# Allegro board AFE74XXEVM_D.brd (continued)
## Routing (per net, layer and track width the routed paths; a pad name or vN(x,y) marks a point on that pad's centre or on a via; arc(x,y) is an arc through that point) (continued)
RXTDD1: length 148.9
  L4_SIG w0.102: 65.15,57.88 60.36,57.88 59.95,58.29 v1(59.95,58.3)
  L4_SIG w0.127: v1(143.21,58.6) 143.21,53.57 140.63,51 139.95,51 134.49,45.54 85.8,45.54 85.09,44.83 79.32,44.83 66.27,57.88 65.15,57.88
  L8_PWR_SIG w0.127: J9.32 143.5,107.85 145.12,106.23 145.12,105.78 144.55,105.21 144.55,90.42 145.21,89.76 145.21,77.82 145.05,77.65 145.05,77.29 145.2,77.13 145.2,73.32 145.21,73.31 145.21,70.59 143.36,68.73 143.36,58.75 v1(143.21,58.6)
RXTDD2: length 115.5
  TOP w0.127: J9.35 145.69,107.85 144.26,106.41 144.26,105.87 144.41,105.72 144.41,103.64 142.37,101.6 142.37,93.95 140.61,92.2 140.61,86.18 139.11,84.67 123.3,84.67 v1(123.29,84.68)
  L4_SIG w0.102: 60.33,71.5 60.33,69.08 v1(59.95,68.7)
  L4_SIG w0.127: v1(123.29,84.68) 122.58,85.39 121.16,85.39 119.33,83.57 111.38,83.57 110.74,82.93 103.89,82.93 103.38,83.44 102.36,83.44 101.85,82.93 99.29,82.93 98.7,83.52 92.36,83.52 92.16,83.32 89.43,83.32 84.62,78.52 77.76,78.52 77.55,78.73 77.18,78.73 76.86,78.4 66.69,78.4 62.25,73.96 62.25,73.94 61.03,72.72 61.03,72.62 60.33,71.92 60.33,71.5
SDCLKOUT5N: length 4.5
  BOTTOM w0.203: U3.23 96.94,90.11 96.85,90.02 95.77,90.02 95.38,89.62 95.38,88.99 95.2,88.81 94.96,88.81 R194.1 94.23,88.93 C257.1
SDCLKOUT5P: length 4.6
  BOTTOM w0.203: C256.1 94.23,88.27 R193.1 95.06,88.48 95.34,88.48 95.71,88.85 95.71,89.49 95.91,89.69 96.85,89.69 96.94,89.6 U3.22
SDCLKOUT7N: length 3.5
  BOTTOM w0.203: C426.1 R291.1 95.67,94.4 96.12,94.4 96.52,94 96.52,93.73 96.7,93.55 97.26,93.55 97.32,93.61 U3.30
SDCLKOUT7P: length 3.5
  BOTTOM w0.203: U3.29 97.32,93.11 97.21,93.22 96.56,93.22 96.19,93.59 96.19,93.87 95.99,94.07 95.67,94.07 R292.1 94.89,93.9 C425.1
SLEEPMODE: length 140.5
  TOP w0.127: v1(143.99,86.44) 144.25,86.44 145.47,87.66 145.47,93.93 146.84,95.3 146.84,102.13 149.59,104.89 149.59,105.91 v1(149.45,106.05)
  L4_SIG w0.102: v1(61.55,66.3) 61.81,66.3 62.19,66.68 62.52,66.68 62.77,66.93 62.77,67.26 63,67.49 63.28,67.49 63.57,67.78 63.57,68.09 63.78,68.3 65.15,68.3
  L4_SIG w0.127: 65.15,68.3 72.87,68.3 74.04,69.47 138.76,69.47 140.18,70.89 v1(140.46,70.89)
  L6_SIG w0.127: v1(149.45,106.05) 150.27,106.05 150.65,106.43 167.44,106.43 J9.62
  L8_PWR_SIG w0.127: v1(140.46,70.89) 140.72,71.15 140.72,74.6 143.27,77.15 143.27,77.68 143.53,77.94 143.53,85.97 v1(143.99,86.44)
SPIACLK: length 209.3
  TOP w0.127: v1(124.16,115.49) 126.62,113.03 126.62,110.8 126.63,110.78 126.63,104.91 126.62,104.9 126.62,93.37 125.45,92.2 125.45,89.87 126.44,88.87 J13.5
  L6_SIG w0.102: v1(54.35,58.3) 54.21,58.3 53.9,57.99 53.9,57.69 53.93,57.66 53.93,56.54 53.71,56.32 49.15,56.32
  L6_SIG w0.127: 49.15,56.32 48.62,56.32 48.29,56.66 45.43,56.66 42.24,53.46 40.77,53.46 40.45,53.15 40.08,53.15 39.77,53.46 35.5,53.46 34.85,54.11 29.15,54.11 26.3,56.96 26.1,56.96 24.01,59.05 23.39,59.05 23.11,59.34 23.11,61.31 22.49,61.93 22.49,68.62 23.05,69.18 23.05,74.17 23.46,74.58 23.46,85.09 33.47,95.1 33.47,95.95 39.36,101.84 41.75,101.84 46.67,106.77 46.67,107.05 46.93,107.31 47.21,107.31 58.69,118.79 61.51,118.79 62.07,118.23 93.92,118.23 94.46,118.77 111.13,118.77 114.2,115.7 123.95,115.7 v1(124.16,115.49)
SPIASDIO: length 196.4
  TOP w0.127: v1(132.44,109.3) 132.16,109.02 132.16,93.78 130.57,92.19 130.57,89.9 131.52,88.95 J13.11
  L6_SIG w0.102: 49.15,59.51 53.24,59.51 53.55,59.2 v1(53.55,59.1)
  L6_SIG w0.127: v1(132.44,109.3) 132.08,109.65 132.08,110.41 131.15,111.34 129.96,111.34 129.78,111.16 129.28,111.16 128.96,111.48 116.66,111.48 114.86,109.68 110.76,109.68 110.72,109.64 110.36,109.64 110.32,109.68 109.58,109.68 109.57,109.67 108.49,109.67 107.72,110.44 101.47,110.44 100.61,111.3 81.71,111.3 81.59,111.18 74.41,111.18 74.12,110.89 73.75,110.89 73.39,111.26 69.69,111.26 69.69,111.26 65.9,111.26 65.77,111.14 65.4,111.14 65.28,111.26 56.06,111.26 48.31,103.51 47.88,103.51 44.45,100.08 44.17,100.08 43.88,99.79 43.88,99.03 41.78,96.93 40.58,96.93 39.83,96.17 37.98,96.17 36.32,94.52 36.32,93.16 34.95,91.79 34.95,91.05 33.24,89.34 32.84,89.34 32.58,89.08 32.58,88.9 30.55,86.88 30.55,86.31 30.22,85.97 30.22,79.84 30.68,79.39 30.68,77.8 28.07,75.19 28.07,74.08 27.66,73.67 27.66,67.44 28.77,66.33 28.77,64.86 27.5,63.59 27.5,60.98 28.92,59.55 28.92,58.97 29.21,58.68 31.49,58.68 32.62,57.55 41.04,57.55 43.37,59.88 48.78,59.88 49.15,59.51
SPIASDO: length 128.7
  L4_SIG w0.102: v1(53.55,57.5) 53.17,57.12 53.17,56.34 52.32,55.5 49.33,55.5 49.15,55.67
  L4_SIG w0.127: 49.15,55.67 48.55,56.28 48.55,56.4 48.29,56.66 48.17,56.66 46.75,58.08 46.75,58.19 45.98,58.95 45.31,58.95 45.05,59.21 45.05,59.78 43.51,61.32 43.51,63.11 44.16,63.76 44.16,65.49 43.9,65.75 43.9,73.9 42.99,74.82 42.99,80.16 42.98,80.17 42.98,80.54 42.99,80.54 v1(42.99,82.66)
  L6_SIG w0.127: v1(121.74,89.26) 121.92,89.26 122.5,89.84 127.94,89.84 J13.8
  L8_PWR_SIG w0.127: v1(42.99,82.66) 43.03,82.66 47.69,87.32 47.69,87.68 48.15,88.15 48.9,88.15 49.17,87.87 54.6,87.87 56.82,90.09 60.93,90.09 61.8,89.23 71.12,89.23 71.18,89.3 71.55,89.3 71.62,89.23 73.52,89.23 73.58,89.3 73.95,89.3 74.02,89.23 84.5,89.23 85.03,88.7 91.11,88.7 92.11,87.69 93.92,87.69 95.11,88.89 97.14,88.89 97.24,88.79 97.24,88.79 97.68,88.35 109.53,88.35 110.14,88.96 117.46,88.96 117.75,89.26 v1(121.74,89.26)
SPIASEN: length 201.3
  TOP w0.127: J13.2 123.88,88.8 122.86,89.81 122.86,91.92 123.57,92.63 123.57,101.49 122.66,102.4 122.66,102.82 121.95,103.53 121.95,114.22 v1(121.39,114.78)
  L6_SIG w0.102: v1(53.55,58.3) 53.52,58.3 53.13,57.91 53.13,57.34 52.87,57.08 49.15,57.08
  L6_SIG w0.127: v1(121.39,114.78) 121.03,115.14 113.97,115.14 111.69,117.42 74.84,117.42 74.19,116.77 72.8,116.77 72.36,117.21 65.86,117.21 65.86,117.21 64.15,117.21 63.91,116.97 62.42,116.97 61.77,117.61 59.18,117.61 47.74,106.17 47.26,106.17 46.1,105.01 46.1,104.8 43.03,101.73 43.03,101.56 42.77,101.3 41.85,101.3 41.11,100.57 38.76,100.57 33.99,95.79 33.99,94.26 29.67,89.95 29.67,89.7 26.48,86.51 26.48,85.71 24.03,83.26 24.03,65.67 23,64.64 23,63.78 23.78,63 23.78,60.09 25.84,58.04 26.38,58.04 29.08,55.34 32.06,55.34 32.64,54.76 34.98,54.76 35.16,54.94 35.57,54.94 36.44,54.06 38.72,54.06 39.28,54.62 41.67,54.62 44.13,57.08 49.15,57.08
SPIBCLK: length 99.3
  L4_SIG w0.102: v1(54.35,68.7) 53.97,69.08 53.43,69.08 53.13,69.38 53.13,71.5
  L4_SIG w0.127: 53.13,71.5 53.13,72.66 53.13,72.66 53.13,72.9 53.66,73.43 53.66,75.21 54.77,76.32 54.77,80.19 v1(57.48,82.91)
  L6_SIG w0.127: v1(122.48,86.74) 123.01,87.27 135.08,87.27 J13.17
  L8_PWR_SIG w0.127: v1(122.48,86.74) 121.36,85.62 101.73,85.62 101.72,85.61 97.32,85.61 97.18,85.76 95.55,85.76 95.41,85.62 85.62,85.62 83.86,83.87 83.01,83.87 82.27,84.61 67.51,84.61 66.29,83.39 61.34,83.39 61.07,83.66 60.19,83.66 59.44,82.91 v1(57.48,82.91)
SPIBSDIO: length 116.6
  L4_SIG w0.102: v1(53.55,67.9) 53.54,67.9 53.13,68.31 53.13,68.86 52.87,69.12 52.55,69.12 52.33,69.34 52.33,71.5
  L4_SIG w0.127: v1(56.46,86.03) 54.05,83.62 54.05,79.4 53.35,78.7 53.35,75.91 52.66,75.22 52.66,74.1 52.82,73.94 52.82,72.95 52.33,72.46 52.33,71.5
  L6_SIG w0.127: J13.23 140.67,87.78 138.79,87.78 137.85,86.84 137.85,86.16 136.92,85.23 122.72,85.23 118.99,88.96 110.76,88.96 108.93,87.13 108.93,86.88 105.88,83.83 105.88,83.33 105.05,82.5 99.75,82.5 97.38,84.87 96.81,84.87 96.55,85.13 96.18,85.13 95.92,84.87 95.55,84.87 95.13,85.29 92.71,85.29 89.71,88.29 87.01,88.29 86.84,88.46 81.74,88.46 81.63,88.34 70.72,88.34 70.36,88.7 69.95,88.7 69.63,88.38 59.54,88.38 59.04,87.88 58.06,87.88 56.46,86.28 v1(56.46,86.03)
SPIBSDO: length 107.3
  L6_SIG w0.127: J13.20 138.07,89.87 135.94,89.87 135.28,89.2 135.28,88.47 134.59,87.78 123.42,87.78 122.62,88.58 121.32,88.58 v1(121.26,88.52)
  L8_PWR_SIG w0.127: v1(121.26,88.52) 121.23,88.48 119.07,88.48 118.03,87.45 113.13,87.45 112.18,86.5 106.01,86.5 105.17,87.34 99.48,87.34 98.77,86.63 91.96,86.63 91.56,87.02 88.39,87.02 88.19,86.82 84.5,86.82 83.6,87.71 69.49,87.71 69.32,87.88 56.74,87.88 v1(55.4,86.54)
  BOTTOM w0.102: 53.14,71.5 53.14,69.91 v1(53.55,69.5)
  BOTTOM w0.127: 53.14,71.5 52.91,71.73 52.91,73.85 52.66,74.1 52.66,74.91 53.19,75.44 53.19,77.21 52.95,77.45 52.95,80.56 53.62,81.23 53.62,84.76 v1(55.4,86.54)
SPIBSEN: length 105.9
  L6_SIG w0.127: J13.14 132.59,90.27 116.45,90.27 116.19,90 113.75,90 113.61,89.87 111.05,89.87 109.47,88.29 108.97,88.29 104.08,83.4 102.12,83.4 101.84,83.12 100.19,83.12 99.85,83.46 99.85,83.66 97.75,85.76 92.93,85.76 89.31,89.37 58.17,89.37 v1(58.14,89.41)
  BOTTOM w0.102: v1(53.55,68.7) 53.92,69.07 54.45,69.07 54.74,69.36 54.74,71.5
  BOTTOM w0.127: v1(58.14,89.41) 57.86,89.13 57.86,87.99 58.39,87.45 58.39,85.29 54.96,81.85 54.96,75.46 54.4,74.9 54.4,74.53 54.74,74.19 54.74,71.5
STAT 0:
  vias: v1(114.02,88.29)
STAT 1:
  vias: v1(114.05,86.39)
SYNC: length 2.7
  BOTTOM w0.381: U3.6 103.59,85.66 102.74,84.81 R196.2
SYNCB0CMOS: length 221.5
  L4_SIG w0.102: 53.97,55.36 53.97,58.46 54.22,58.72 54.53,58.72 54.91,59.1 v1(55.15,59.1)
  L4_SIG w0.127: 53.97,55.36 53.97,53.58 56.5,51.05 57.05,51.05 58.89,49.22 58.91,49.22 60.55,47.58 60.55,46.99 61.18,46.36 66.89,46.36 69.13,44.12 69.33,44.12 69.62,43.83 69.62,43.63 71.67,41.57 71.67,41.37 78.43,34.62 102.65,34.62 103.33,35.3 103.33,35.89 105.72,38.28 131.24,38.28 131.4,38.44 131.79,38.44 131.95,38.28 148.48,38.28 148.5,38.26 148.87,38.26 148.89,38.28 152.6,38.28 152.91,37.97 189.41,37.97 190.73,39.29 202.08,39.29 203.82,37.55 v1(209.56,37.55)
  L8_PWR_SIG w0.102: 213.55,62.26 209.56,58.27 209.56,38.1
  L8_PWR_SIG w0.127: 209.56,38.1 v1(209.56,37.55) ; v2(210.19,81.91) 210.26,81.91 213.55,78.63 213.55,75.22 213.68,75.09 213.68,74.72 213.55,74.59 213.55,72.75 213.75,72.55 213.75,72.18 213.55,71.98 213.55,62.26
SYNCB1CMOS: length 176.7
  L6_SIG w0.102: v1(59.15,57.5) 59.21,57.5 59.59,57.12 63.27,57.12 63.57,56.82 63.57,56.54 63.8,56.31 65,56.31 65.15,56.16 ; v2(210.19,80.64) 211.89,78.94 211.89,73.89 211.79,73.79 211.79,73.43 211.89,73.33 211.89,62.69 203.48,54.28
  L6_SIG w0.127: 65.15,56.16 67.34,53.97 203.18,53.97 203.48,54.28
SYNCB2CMOS: length 169.8
  L6_SIG w0.102: 203.48,78.77 209.52,78.77 v2(210.19,78.11)
  L6_SIG w0.127: v1(59.36,78.13) 60.45,79.23 64.82,79.23 64.94,79.11 67.88,79.11 68.09,79.32 73.03,79.32 77.27,75.08 77.49,75.08 80.03,72.54 100.79,72.54 101.9,73.65 102.03,73.65 107.17,78.79 203.45,78.79 203.48,78.77
  BOTTOM w0.102: 56.38,71.5 56.38,69.38 56.07,69.07 55.79,69.07 55.58,68.86 55.58,68.33 v1(55.15,67.9)
  BOTTOM w0.127: 56.38,71.5 56.38,72.43 56.69,72.74 56.69,73.11 56.38,73.43 56.38,74.99 58.22,76.84 58.67,76.84 59.36,77.53 v1(59.36,78.13)
SYNCB3CMOS: length 163.3
  L6_SIG w0.102: v2(210.19,76.83) 209.45,77.57 203.48,77.57 ; 59.57,71.5 59.57,69.92 v1(59.15,69.5)
  L6_SIG w0.127: 59.57,71.5 59.57,73.84 64.4,78.67 65.04,78.67 65.3,78.4 73.11,78.4 78.47,73.04 78.47,72.84 79.2,72.11 103.07,72.11 106.22,75.26 106.22,75.57 108.89,78.23 202.69,78.23 203.35,77.57 203.48,77.57
SYSREF+: length 3.6
  BOTTOM w0.203: U3.14 99.58,85.86 99.67,85.78 99.67,84.95 100.1,84.51 100.1,83.74 R174.1 99.95,83.54 R172.1
SYSREF-: length 3.6
  BOTTOM w0.203: U3.13 100.08,85.89 100,85.8 100,85.08 100.43,84.65 100.43,83.72 R173.1 100.56,83.54 R169.1
SYSREF-N: length 13
  L6_SIG w0.102: 49.15,62.59 49.25,62.59 49.35,62.69 51.28,62.69 51.48,62.88 51.62,62.88 51.82,62.68 52.07,62.68 52.28,62.89 52.42,62.89 52.59,62.72 52.6,62.72 52.63,62.68 52.88,62.68 53.08,62.88 53.22,62.88 53.42,62.68 53.82,62.68 53.93,62.79 53.93,63.32 53.82,63.43 53.82,63.63 54.09,63.9 v1(54.35,63.9)
  L6_SIG w0.127: 49.15,62.59 44.22,62.59 44.09,62.71 v1(44.09,62.84)
  BOTTOM w0.203: v1(44.09,62.84) 43.97,62.71 R13.2
SYSREF-P: length 13
  L6_SIG w0.102: v1(54.35,63.1) 54.77,62.68 54.77,62.16 54.53,61.92 49.33,61.92 49.15,62.1
  L6_SIG w0.127: v1(44.09,61.95) 44.09,62.03 44.22,62.15 49.1,62.15 49.15,62.1
  BOTTOM w0.203: R12.2 43.97,62.08 v1(44.09,61.95)
SYSREFN: length 94.7
  L6_SIG w0.127: v1(42.7,62.71) 42.6,62.61 42.09,62.61 41.33,61.85 41.33,61.44 40.26,60.38 36.37,60.38 36.26,60.49 36.26,60.53 36.15,60.65 35.99,60.65 35.88,60.53 35.88,60.49 35.77,60.38 35.41,60.38 34.32,61.47 34.32,62.09 34.43,62.2 34.46,62.2 34.57,62.31 34.57,62.47 34.46,62.58 34.43,62.58 34.32,62.69 34.32,63.07 35.33,64.08 35.33,66.32 38.6,69.6 38.96,69.6 39.07,69.48 39.07,69.48 39.18,69.37 39.34,69.37 39.45,69.48 39.45,69.48 39.57,69.6 40.67,69.6 46.81,75.73 47.11,75.73 48.6,77.22 49,77.22 50.77,78.99 50.77,79.38 52.69,81.3 52.69,81.87 55.88,85.06 61.7,85.06 62.55,85.91 65.17,85.91 66.02,85.06 69.11,85.06 69.12,85.06 70.35,85.06 70.35,85.06 72.18,85.06 72.45,85.33 83.48,85.33 83.7,85.55 84,85.55 84.01,85.56 90.46,85.56 91.47,84.56 91.72,84.56 92.95,83.32 96.48,83.32 97.41,82.4 97.41,81.59 98.53,80.46 99.89,80.46 100.47,81.04 100.47,81.57 v1(100.58,81.69)
  BOTTOM w0.203: v1(100.58,81.69) 100.46,81.81 100.46,82.22 R169.2
SYSREFP: length 94.7
  L6_SIG w0.127: v1(42.7,62.08) 42.6,62.18 42.27,62.18 41.76,61.67 41.76,61.26 40.44,59.95 35.23,59.95 33.88,61.29 33.88,63.25 34.9,64.26 34.9,66.5 38.42,70.03 40.49,70.03 46.63,76.16 46.93,76.16 48.42,77.66 48.83,77.66 50.34,79.17 50.34,79.56 52.26,81.48 52.26,82.05 55.7,85.49 61.52,85.49 62.37,86.34 65.35,86.34 66.19,85.5 69.29,85.5 69.3,85.49 70.17,85.49 70.17,85.5 72,85.5 72.27,85.76 83.3,85.76 83.52,85.99 83.82,85.99 83.83,85.99 90.64,85.99 91.64,84.99 91.9,84.99 93.13,83.76 96.66,83.76 97.84,82.58 97.84,81.77 98.71,80.89 99.71,80.89 100.04,81.22 100.04,81.57 v1(99.92,81.69)
  BOTTOM w0.203: v1(99.92,81.69) 100.08,81.84 100.08,82.19 R172.2
TCLK: length 113.9
  L4_SIG w0.102: 65.15,62.72 61.92,62.72 61.55,63.09 v1(61.55,63.1)
  L4_SIG w0.127: 65.15,62.72 66.14,62.72 66.56,62.29 70.32,62.29 72.75,59.87 142.37,59.87 143.84,61.34 v1(144.04,61.34)
  L8_PWR_SIG w0.127: J10.2 145.81,87.85 145.81,85.86 146.08,85.6 146.08,75.99 145.53,75.44 145.53,75.08 146.33,74.28 146.33,71.11 145.53,70.31 145.53,69.99 144.91,69.37 144.91,62.2 v1(144.04,61.34)
TDI: length 115
  L4_SIG w0.102: v1(61.55,63.9) 61.65,63.9 62.03,63.52 64.11,63.52 64.37,63.78 64.37,64.06 64.62,64.31 65.15,64.31
  L4_SIG w0.127: 65.15,64.31 65.56,64.72 72.97,64.72 74.88,62.81 147.36,62.81 148.89,64.34 v1(148.89,64.74)
  L8_PWR_SIG w0.127: J10.5 149.3,87.78 148.35,86.83 148.35,84.97 148.02,84.64 148.02,81.26 148.44,80.84 148.44,75.53 148.5,75.47 148.5,75.1 148.44,75.04 148.44,65.2 v1(148.89,64.74)
TDO: length 118.3
  L6_SIG w0.102: 65.15,62.7 65.13,62.68 62.19,62.68 61.93,62.42 61.93,61.88 v1(61.55,61.5)
  L6_SIG w0.127: v1(150.95,64.62) 150.14,64.62 148.69,66.07 108.81,66.07 108.24,65.49 108.24,65.17 107.98,64.91 107.66,64.91 106.1,63.35 105.9,63.35 105.63,63.08 78.78,63.08 78.76,63.11 70.59,63.11 70.47,62.98 68.52,62.98 68.15,63.35 65.8,63.35 65.15,62.7
  L8_PWR_SIG w0.127: v1(150.95,64.62) 151.1,64.77 151.1,69.49 152.11,70.5 152.11,79.69 151.74,80.05 151.74,84.66 150.89,85.51 150.89,87.85 J10.8
TMS: length 115.4
  L4_SIG w0.102: v1(61.55,65.5) 61.55,65.42 61.86,65.12 63.31,65.12 63.57,65.38 63.57,65.66 63.83,65.92 64.11,65.92 64.36,66.17 64.36,66.45 64.63,66.72 65.15,66.72
  L4_SIG w0.127: 65.15,66.72 65.37,66.5 75.72,66.5 75.79,66.43 76.16,66.43 76.24,66.52 78.85,66.52 78.95,66.42 151.66,66.42 152.78,67.54 v1(152.78,67.79)
  L8_PWR_SIG w0.127: v1(152.78,67.79) 153.52,68.53 153.52,70.93 153.64,71.06 153.65,71.06 153.96,71.37 153.96,85.3 153.52,85.74 153.52,85.77 153.43,85.86 153.43,87.85 J10.11
TRST: length 120.1
  L4_SIG w0.102: v1(61.55,64.7) 61.93,64.32 63.31,64.32 63.57,64.58 63.57,64.86 63.83,65.12 64.11,65.12 64.37,65.38 64.37,65.66 64.63,65.92 65.15,65.92
  L4_SIG w0.127: v1(155.93,67.84) 155.47,67.84 153.67,66.04 65.27,66.04 65.15,65.92
  L8_PWR_SIG w0.127: J10.14 156.92,88.65 157.87,87.69 157.87,85.35 157.26,84.74 157.26,75.1 157.72,74.64 157.72,70.42 155.93,68.63 v1(155.93,67.84)
  BOTTOM w0.127: R30.1 156.95,88.77 J10.14
TX1ENB: length 220.1
  TOP w0.127: v1(162.89,116.36) 162.89,110.85 162.83,110.78 162.83,108.8 J9.56
  L6_SIG w0.102: 49.15,57.77 49.3,57.92 52.11,57.92 52.13,57.94 52.33,57.94 52.69,58.3 v1(52.75,58.3)
  L6_SIG w0.127: 49.15,57.77 48.92,57.54 46.14,57.54 45.71,57.97 43.57,57.97 42.28,56.68 40.91,56.68 40.86,56.73 40.5,56.73 40.45,56.68 35.94,56.68 34.79,55.52 33.59,55.52 33.35,55.76 30.49,55.76 28.71,57.54 27.71,57.54 24.35,60.91 24.35,62.05 24.7,62.4 24.7,63.33 25.27,63.9 25.27,69.73 25.29,69.75 25.29,71.78 25.46,71.95 25.46,72.32 25.2,72.59 25.2,75.47 24.63,76.04 24.63,82.31 31.09,88.78 31.09,90.6 34.53,94.04 34.53,94.82 36.84,97.13 36.84,97.62 37.94,98.72 38.43,98.72 39.96,100.25 41.82,100.25 42.46,100.89 42.89,100.89 43.86,101.85 43.86,101.86 44.12,102.12 44.13,102.12 45.51,103.5 46.1,103.5 46.36,103.77 46.36,103.91 47.41,104.96 47.64,104.96 57.38,114.7 57.38,114.98 58.42,116.01 62.51,116.01 62.67,116.17 95.79,116.17 96.42,115.54 97.08,115.54 97.46,115.93 112.33,115.93 113.92,114.34 135.67,114.34 135.93,114.08 147.89,114.08 150.47,116.66 162.59,116.66 v1(162.89,116.36)
TX1N: length 14.6
  TOP w0.102: v1(63.15,57.5) 63.15,57.54 63.54,57.93 64.97,57.93 65.15,57.75
  TOP w0.203: 65.15,57.75 65.47,57.43 66.19,57.43 66.4,57.22 66.65,57.22 66.74,57.31 67,57.31 67.18,57.13 67.18,56.88 67.08,56.79 67.08,56.54 72.47,51.16 73.96,51.16 C14.2
TX1P: length 14.6
  TOP w0.102: v1(62.35,57.5) 62.49,57.5 62.92,57.07 62.99,57.07 62.99,57.07 65.15,57.07
  TOP w0.203: C13.2 73.96,50.83 72.33,50.83 66.06,57.1 65.47,57.1 65.44,57.07 65.15,57.07
TX2ENB: length 154.6
  L6_SIG w0.127: v1(56.21,99.47) 58.3,99.47 58.54,99.71 59.71,99.71 60.54,100.53 60.54,101.09 64.24,104.79 64.24,105.24 64.65,105.65 65.15,105.65 67.04,107.55 67.54,107.55 67.76,107.33 71.79,107.33 72.16,106.95 73.72,106.95 74.09,107.33 89.85,107.33 90.65,108.13 94.23,108.13 94.92,107.44 106.38,107.44 107.06,106.76 110.59,106.76 113.49,103.86 126.03,103.86 126.72,104.55 126.72,105.79 127.28,106.35 133.86,106.35 134.11,106.1 135.08,106.1 135.41,106.43 141.05,106.43 141.71,107.09 142.7,107.09 143.1,106.68 146.61,106.68 147.17,107.24 147.17,107.9 148.11,108.84 149.43,108.84 149.68,109.08 150.04,109.08 150.29,108.84 165.4,108.84 166.32,107.92 J9.59
  BOTTOM w0.102: 51.54,71.5 51.54,70.18 51.79,69.93 52.07,69.93 52.37,69.62 52.37,69.19 52.75,68.81 v1(52.75,68.7)
  BOTTOM w0.127: 51.54,71.5 51.41,71.62 51.41,76.52 51.15,76.79 51.15,80.42 51.56,80.84 51.56,84.89 54.71,88.03 54.71,97.06 56.21,98.56 v1(56.21,99.47)
TX2N: length 14
  TOP w0.102: 65.15,59.36 65.02,59.49 63.58,59.49 63.19,59.1 v1(63.15,59.1)
  TOP w0.203: 65.15,59.36 65.51,59 65.87,59 66.05,59.18 66.05,59.33 66.23,59.51 66.48,59.51 66.66,59.33 66.66,59.18 66.84,59 68.13,59 72.93,54.2 73.96,54.2 C16.2
TX2P: length 14
  TOP w0.102: v1(62.35,59.1) 62.78,58.67 65.15,58.67
  TOP w0.203: 65.15,58.67 68,58.67 72.8,53.87 73.96,53.87 C15.2
TX3N: length 13.4
  TOP w0.102: v1(63.15,60.7) 63.42,60.7 63.79,61.07 65.04,61.07 65.15,60.96
  TOP w0.203: C18.2 73.96,57.25 72.4,57.25 69.05,60.6 66.8,60.6 66.62,60.78 66.62,60.93 66.44,61.11 66.19,61.11 66.01,60.93 66.01,60.78 65.83,60.6 65.51,60.6 65.15,60.96
TX3P: length 13.4
  TOP w0.102: v1(62.35,60.7) 62.78,60.27 62.99,60.27 65.15,60.27
  TOP w0.203: C20.2 73.96,56.92 72.26,56.92 68.91,60.27 65.15,60.27
TX4N: length 12.7
  TOP w0.102: v1(63.15,62.3) 63.58,62.73 64.97,62.73 65.15,62.55
  TOP w0.203: 65.15,62.55 65.52,62.18 65.76,62.18 65.94,62.36 65.94,62.48 66.12,62.66 66.37,62.66 66.55,62.48 66.55,62.36 66.73,62.18 71.15,62.18 73.03,60.3 73.94,60.3 C22.2
TX4P: length 12.8
  TOP w0.102: 65.15,61.85 65.13,61.87 62.78,61.87 v1(62.35,62.3)
  TOP w0.203: C24.2 73.94,59.97 72.89,59.97 71.01,61.85 65.15,61.85
TX5N: length 12.7
  TOP w0.102: 65.15,64.45 65.02,64.33 63.52,64.33 v1(63.15,64.7)
  TOP w0.203: 65.15,64.45 65.21,64.51 65.21,64.55 65.4,64.74 65.62,64.74 65.8,64.57 65.8,64.42 65.98,64.24 66.23,64.24 66.41,64.42 66.41,64.57 66.59,64.74 70.68,64.74 72.41,63.02 73.96,63.02 C27.2
TX5P: length 12.7
  TOP w0.102: 65.15,65.07 62.72,65.07 v1(62.35,64.7)
  TOP w0.203: 65.15,65.07 70.82,65.07 72.54,63.35 73.96,63.35 C28.2
TX6N: length 12.1
  TOP w0.102: 65.15,66.05 64.98,65.89 63.56,65.89 v1(63.15,66.3)
  TOP w0.203: C32.2 73.96,66.07 71.73,66.07 71.45,66.34 66.83,66.34 66.65,66.17 66.65,66.02 66.47,65.84 66.22,65.84 66.04,66.02 66.04,66.17 65.86,66.34 65.44,66.34 65.15,66.05
TX6P: length 12.1
  TOP w0.102: 65.15,66.67 62.72,66.67 v1(62.35,66.3)
  TOP w0.203: C30.2 73.96,66.4 71.87,66.4 71.59,66.67 65.15,66.67
TX7N: length 12.4
  TOP w0.102: 65.15,67.65 64.97,67.47 64.53,67.47 64.48,67.53 63.52,67.53 v1(63.15,67.9)
  TOP w0.203: 65.15,67.65 65.49,68 65.95,68 66.13,67.82 66.13,67.69 66.31,67.51 66.56,67.51 66.74,67.69 66.74,67.82 66.92,68 71.75,68 72.87,69.11 73.96,69.11 C35.2
TX7P: length 12.5
  TOP w0.102: v1(62.35,67.9) 62.75,68.3 64.5,68.3 64.53,68.33 65.15,68.33
  TOP w0.203: C36.2 73.96,69.44 72.74,69.44 71.62,68.33 65.15,68.33
TX8N: length 13.1
  TOP w0.102: 65.15,69.31 65.15,69.25 65.02,69.13 63.52,69.13 v1(63.15,69.5)
  TOP w0.203: C38.2 73.96,72.16 72.98,72.16 70.37,69.54 66.84,69.54 66.66,69.37 66.66,69.22 66.48,69.04 66.23,69.04 66.05,69.22 66.05,69.37 65.87,69.54 65.39,69.54 65.15,69.31
TX8P: length 13.1
  TOP w0.102: 65.15,69.87 62.72,69.87 v1(62.35,69.5)
  TOP w0.203: 65.15,69.87 70.23,69.87 72.85,72.49 73.96,72.49 C40.2
TXAM: length 20.4
  TOP w0.203: U1.C20 49.3,57.25 46.87,57.25 R137.2 46.81,57.25 45.95,57.25 42.88,54.18 42.88,52.22 40.91,50.26 L27.1 40.53,50.05 40.47,50.01 36.19,47.45 36.14,47.42 35.77,47.48 35.51,47.78 34.6,47.78 T20.4
TXAP: length 20.4
  TOP w0.203: U1.B20 49.33,56.92 46.96,56.92 46.96,56.92 R137.1 46.84,56.92 46.09,56.92 43.21,54.04 43.21,51.94 40.97,49.71 L28.2 40.59,49.7 36.39,47.19 36.2,46.69 36.35,46.32 36.08,45.62 T20.6
TXBM: length 20.4
  TOP w0.203: U1.F20 49.36,60.09 R141.1 43.48,60.09 40.31,56.92 38.15,56.92 L34.2 37.72,56.95 32.64,56.95 32.4,56.71 32.4,56.41 31.83,55.83 T21.6
TXBP: length 20.4
  TOP w0.203: T21.4 31.82,58.37 32.4,57.79 32.4,57.56 32.69,57.28 37.72,57.28 L33.1 38.2,57.25 40.17,57.25 43.35,60.42 46.68,60.42 46.71,60.45 R141.2 46.82,60.45 46.91,60.45 46.94,60.42 49.27,60.42 U1.G20
TXCM: length 20.4
  TOP w0.203: T22.4 36.09,81.58 36.35,80.63 36.26,80.48 36.35,80.13 40.79,77.57 L35.1 41.15,77.6 41.15,77.42 42.57,76 44.4,76 46.89,73.51 46.89,71.86 47.55,71.2 R145.2 47.55,71.18 47.93,70.8 47.93,70.69 48.79,69.83 49.08,69.83 U1.W20
TXCP: length 20.4
  TOP w0.203: T22.6 34.86,79.36 35.68,79.58 35.8,79.78 36.14,79.87 40.63,77.28 L36.2 41,77.09 42.42,75.67 44.26,75.67 46.56,73.37 46.56,71.7 R145.1 47.6,70.66 47.6,70.55 48.65,69.5 U1.V20
TXDM: length 20.4
  TOP w0.203: U1.P20 49.34,66.51 46.83,66.51 R149.1 46.8,66.51 43.6,66.51 40.51,69.6 38.23,69.6 L42.2 37.76,69.67 32.77,69.67 32.41,69.31 32.41,69.02 31.93,68.54 T23.6
TXDP: length 20.4
  TOP w0.203: U1.R20 49.29,66.84 46.83,66.84 R149.2 46.8,66.84 43.74,66.84 40.65,69.93 38.27,69.93 L41.1 37.86,70 32.69,70 32.43,70.26 32.43,70.59 31.94,71.08 T23.4
TXDSASW: length 154.3
  TOP w0.127: J9.44 152.6,107.85 151.36,109.09 150.9,109.09 150.01,109.98 150.01,112.29 148.89,113.41 v1(148.89,119.94)
  L8_PWR_SIG w0.102: 55.65,71.5 55.53,71.38 55.53,69.08 v1(55.15,68.7)
  L8_PWR_SIG w0.127: 55.65,71.5 57,72.85 57,73.54 60.73,77.27 72.47,77.27 73.93,78.73 84.47,78.73 85.45,79.71 97.08,79.71 98.07,80.7 108.51,80.7 109.42,81.61 120.93,81.61 123.74,84.42 123.74,85.03 122.95,85.81 122.95,92.34 123.7,93.09 123.7,100.3 119.41,104.6 119.41,110.97 121.69,113.26 132.51,113.26 135.36,116.1 144.65,116.1 145.87,117.32 145.87,117.93 147.88,119.94 v1(148.89,119.94)
TXTDD1: length 150.5
  L4_SIG w0.102: v1(52.75,57.5) 52.37,57.12 52.37,56.56 52.07,56.26 51.33,56.26 51.31,56.28 49.26,56.28 49.15,56.38 49.15,56.47
  L4_SIG w0.127: 49.15,56.47 48.08,57.54 47.8,57.54 47.54,57.8 47.54,58.08 46.71,58.92 46.63,58.92 46.32,59.23 46.32,68.94 46.46,69.08 46.46,70.57 46.7,70.81 46.7,73.71 46.14,74.27 46.14,77.74 44.81,79.07 44.81,80.96 45.16,81.31 45.16,95.53 v1(44.78,95.91)
  L6_SIG w0.127: J9.26 137.8,107.85 136.68,108.97 132.73,108.97 132.58,108.81 124.97,108.81 124.36,108.2 124.36,107.47 123.27,106.38 115.88,106.38 115.58,106.09 112.66,106.09 110.91,107.84 107.76,107.84 107.11,108.48 100.97,108.48 100.65,108.8 98.72,108.8 98.67,108.85 96.03,108.85 95.14,109.74 81.32,109.74 80.92,109.34 79.27,109.34 79.01,109.6 78.64,109.6 78.38,109.34 76.73,109.34 76.47,109.6 76.1,109.6 75.55,109.05 73.35,109.05 73.12,109.29 70.38,109.29 70.06,109.61 67.49,109.61 65.81,107.93 64.48,107.93 57.2,100.66 56.54,100.66 51.79,95.91 v1(44.78,95.91)
TXTDD2: length 124.8
  L6_SIG w0.127: v1(57.18,100.08) 57.54,100.08 64.51,107.04 65.96,107.04 66.79,107.88 67.16,107.88 67.84,108.56 93.95,108.56 94.15,108.76 95.45,108.76 95.89,108.33 96.63,108.33 96.73,108.43 97.1,108.43 97.14,108.39 100.14,108.39 100.58,107.95 106.63,107.95 107.25,107.33 110.73,107.33 113.7,104.36 123.6,104.36 124.26,105.02 124.26,106.02 125.07,106.83 133.81,106.83 134.19,107.21 134.85,107.21 135.2,106.86 139.93,106.86 J9.29
  BOTTOM w0.102: v1(52.75,69.5) 52.75,69.7 52.35,70.1 52.35,71.22 52.07,71.5
  BOTTOM w0.127: 52.07,71.5 51.93,71.64 51.93,77.21 51.83,77.31 51.83,77.94 52.16,78.27 52.16,84.47 55.33,87.64 55.33,97.03 57.09,98.78 57.09,99.99 v1(57.18,100.08)
U16_FB: length 8.9
  TOP w0.305: R243.1 156.69,17.12 ; U16.2 155.21,14.99 C340.2 155.3,15.01 155.7,15.42 155.7,15.43 155.85,15.58 155.87,15.58 R237.2
  TOP w0.508: R321.1 156.69,17.12 156.41,16.84 R243.1 R245.2 R237.2 R239.2
U16_SW: length 1.1
  TOP w0.305: U16.7 152.71,12.41 153.21,12.41 U16.6
USB_DM: length 10.6
  TOP w0.203: R211.2 193.83,114.45 C291.1
  TOP w0.229: U5.7 192.07,107 192.13,107.06 192.68,107.06 193.56,107.94 193.56,113.63 193.75,113.82 C291.1
USB_DP: length 10
  TOP w0.203: C290.1 192.91,114.45 R212.2
  TOP w0.229: U5.8 192.07,107.5 192.13,107.44 192.52,107.44 193.18,108.1 193.18,113.63 192.99,113.82 C290.1
USB_EECLK: length 3
  TOP w0.127: U5.62 187.81,99.14 U8.2
  vias: v1(187.83,98.55)
USB_EECS: length 3.1
  TOP w0.127: U8.1 188.48,100.37 188.31,100.53 U5.63
  vias: v1(188.54,99.59)
USB_REF: length 1.6
  BOTTOM w0.254: R214.1 189.24,106.5 v3(190.69,106.5)
USB_RST: length 1.8
  TOP w0.305: v1(188.87,110.49) 188.88,110.5 U5.14
VADJ:
  vias: v1(212.62,91.74) v2(206.38,38.73) v2(207.65,40) v2(208.92,38.73) v2(210.19,40)
VIO_B_M2C:
  vias: v2(203.84,38.73) v2(205.11,40)
VREF_A_M2C: length 8.8
  TOP w0.254: v2(206.38,88.27) 206.38,89.81 TP4.1
VREF_B_M2C: length 4.9
  TOP w0.254: TP5.1 198.98,88.27 v2(203.84,88.27)
Y2_N: length 5.9
  BOTTOM w0.381: R184.1 103.84,102.77 R185.1 103.84,104.22 104.22,104.6 106.1,104.6 Y1.4
Y2_P: length 6.1
  BOTTOM w0.381: R178.1 103.17,102.77 R179.1 103.17,104.52 105.69,107.03 Y1.5
YO2_N: length 0.7
  BOTTOM w0.381: C251.1 R184.2
YO2_P: length 0.7
  BOTTOM w0.381: C244.1 R178.2
N16791764: length 5.2
  TOP w0.305: J33.1 193.24,119.13 194.74,117.63 R210.2
N16791900: length 11.5
  BOTTOM w0.305: v3(190.73,105.51) v3(189.92,105.51) 189.99,105.44 C282.1 190.65,105.44 v3(190.73,105.51) ; v3(190.73,105.51) 191.01,105.23
  BOTTOM w0.508: 190.2,105.23 189.99,105.44 ; 190.2,105.23 190.63,104.8 FB14.2 ; 190.2,105.23 C283.1 191.67,105.23 ; FB14.2 192.79,104.83 192.79,105.21 ; FB14.2 192.81,105.21 192.79,105.21 ; 192.79,105.21 192.79,105.23 191.67,105.23 ; 191.67,105.23 192.81,104.09
  BOTTOM w0.762: FB14.2 FB15.2
N16791904: length 3.9
  BOTTOM w0.305: C272.1 191.08,108 v3(190.2,108)
  BOTTOM w0.508: C272.1 190.22,108.03 v3(190.2,108)
  BOTTOM w0.762: FB12.2 192.99,107.77 191.36,107.77 C272.1
  vias: v3(191.26,108)
N16792068: length 1.7
  BOTTOM w0.305: R216.2 R215.1 R213.2
N16792392: length 0.8
  BOTTOM w0.127: R220.2 R219.1
  vias: v1(186.53,99.13)
N16935212: length 6
  TOP w0.127: U5.21 186.81,115.95 184.72,118.05 184.29,118.05 U6.15
N16935240: length 13.9
  TOP w0.127: U6.20 v1(183.4,121.14) ; U5.16 v1(190.69,112.26)
  BOTTOM w0.127: v1(190.69,112.26) 185.14,117.81 185.14,120.14 184.1,121.18 183.44,121.18 v1(183.4,121.14)
N16935242: length 7.7
  TOP w0.127: U5.18 188.31,115.5 184.73,119.08 184.31,119.08 U6.17
N17033323: length 1.1
  BOTTOM w0.508: R209.1 194.46,103.61 FB15.1
N17033325:
  vias: v1(196.47,103.61)
N17828171:
  vias: v1(195.61,93.11) v1(195.61,91.84) v1(196.8,93.06) v1(196.83,91.81) v1(197.97,93.08) v1(198,91.84)
N17829143: length 5
  TOP w0.305: U4.3 193.49,89.77 192.82,89.09 190.99,89.09 190.45,89.63 R208.1
N17906763: length 3
  TOP w0.381: J31.1 103.4,81.43 102.74,82.09 v1(102.74,82.96)
N18051729: length 6.6
  TOP w0.127: U5.38 178.34,109 178.16,108.81 178.16,108.15 175.53,105.53 U9.20
N18051775: length 7.3
  TOP w0.127: U9.18 v1(177.13,103.74)
  BOTTOM w0.127: v3(179.44,108.5) 179.43,108.48 178.03,108.48 177.13,107.59 v1(177.13,103.74)
N18051825: length 7.1
  BOTTOM w0.127: v3(176.61,103.24) 177.26,103.24 177.58,103.55 177.58,107.45 178.13,108 179.44,108 v3(179.44,108)
N18051839: length 7
  BOTTOM w0.127: v3(176.61,102.74) 177.26,102.74 177.9,103.38 177.9,107.14 178.26,107.49 179.44,107.49 v3(179.44,107.5)
N18199775: length 1.9
  BOTTOM w0.381: C252.1 103.84,99.01 R186.1 R181.2 103.84,100.84 C251.2
N18276385: length 12.5
  TOP w0.203: v1(98.35,96.62) 98.92,96.62 99.12,96.82 99.12,100.92 96.55,103.49 96.3,103.49 96.2,103.39 95.95,103.39 95.77,103.57 95.77,103.82 95.87,103.92 95.87,104.17 95.7,104.34 95.2,104.34 v1(95.05,104.19)
  BOTTOM w0.203: v1(95.05,104.19) 94.88,104.36 94.59,104.36 94.51,104.27 U2.11
N18284119: length 12.5
  TOP w0.203: v1(100.23,96.62) 99.66,96.62 99.45,96.82 99.45,101.05 95.83,104.67 95.22,104.67 v1(95.05,104.85)
  BOTTOM w0.203: U2.10 94.51,104.77 94.59,104.69 94.88,104.69 v1(95.05,104.85)
N18332593: length 1.6
  BOTTOM w0.305: v1(89.94,105.56) 90.23,105.27 U2.4 ; U2.5 v1(90.96,106.12) ; U2.1 v1(90.55,103.38)
N18332757: length 4.6
  TOP w0.127: U5.23 185.78,113.41 185.78,116.03 184.76,117.04 U6.13
N18476239: length 12.6
  TOP w0.508: v1(104.04,109.52) 109.7,103.86 JP1.1
N18554997: length 1.5
  TOP w0.305: D12.1 179.15,13.72 R221.2
N18555159: length 3.2
  TOP w0.508: v5(188.26,14.6) 188.26,16.21 187.91,16.56 186.84,16.56 U12.4
N18858492: length 1.4
  BOTTOM w0.381: v1(36.63,61.62) 37.47,61.62 R322.2
N18858499: length 1.8
  BOTTOM w0.381: R4.1 R7.1 C4.2
N18858501: length 1.4
  BOTTOM w0.381: v1(36.63,63.04) 37.57,63.04 R323.2
N18864728: length 0.9
  TOP w0.305: Q22.1 R204.2
N18864745: length 54.2
  L4_SIG w0.127: v1(201.19,30.68) 196.72,30.68 195.88,29.85 v1(192.84,29.85)
  L8_PWR_SIG w0.102: 203.48,52.76 203.48,53.01 212.04,61.57 212.04,65.99 v2(212.73,66.67)
  L8_PWR_SIG w0.127: 203.48,52.76 198.82,48.11 198.4,48.11 193.12,42.82 193.12,33.72 192.6,33.2 192.6,30.09 v1(192.84,29.85)
N18864749: length 0.9
  TOP w0.305: Q23.1 R206.2
N18864761: length 45.1
  L8_PWR_SIG w0.127: v1(191.34,30.76) 190.42,31.67 190.42,41.29 199.59,50.46 199.76,50.46 208.25,58.95 208.25,59.21 210.92,61.87 210.92,66.14 v2(211.46,66.67)
N18864763: length 54
  L4_SIG w0.127: v1(196.04,30.73) 195.63,30.33 192.41,30.33 v1(191.92,29.85)
  L8_PWR_SIG w0.102: v2(211.46,67.94) 209.75,66.24 209.75,61.79 203.48,55.52
  L8_PWR_SIG w0.127: v1(191.92,29.85) 191.11,29.85 189.92,31.04 189.92,41.28 189.98,41.34 189.98,41.71 189.92,41.78 189.92,42.8 194.96,47.84 195.87,47.84 199.57,51.54 199.57,52.19 201.95,54.57 202.98,54.57 203.24,54.83 203.24,55.28 203.48,55.52
N18864798: length 0.9
  TOP w0.305: R203.2 Q22.3
N18864814: length 0.9
  TOP w0.305: Q21.1 R202.2
N18865554: length 2.2
  TOP w0.305: D9.2 196.55,35.92 R203.1
N18865572: length 2.2
  TOP w0.305: D8.2 201.7,35.86 R201.1
N18865624: length 2.2
  TOP w0.305: D10.2 191.85,35.94 R207.1
N18865630: length 4
  TOP w0.127: R205.1 202.92,64.77 203.48,64.77
  TOP w0.152: 203.48,64.77 205.74,64.77 v2(206.38,65.41)
N18883805: length 2.9
  BOTTOM w0.381: v1(32.3,44.96) C187.2 ; C187.2 C189.2 ; C187.2 32.77,46.32
N18883857: length 1.8
  TOP w0.381: R136.2 R138.1 C184.2
N18883928: length 1.8
  TOP w0.381: R140.2 R142.1 C195.2
N18883944: length 3
  BOTTOM w0.381: v1(28.2,57.1) C199.2 ; C199.2 C201.2 ; C199.2 C198.2
N18884373: length 2.6
  TOP w0.381: T20.3 C185.2 C184.1
N18884375: length 2.8
  TOP w0.381: T21.3 C197.2 C195.1
N18885333: length 2.8
  BOTTOM w0.381: C206.2 33.38,81.74 C208.2 ; C206.2 v1(32.37,82.26) ; C206.2 C205.2
N18885345: length 1.8
  TOP w0.381: R144.2 R146.1 C202.2
N18885353: length 1.8
  TOP w0.381: C214.2 R150.1 R148.2
N18885357: length 2.9
  BOTTOM w0.381: v1(28.2,69.81) C218.2 ; C218.2 C220.2 ; C218.2 C217.2
N18885439: length 2.7
  TOP w0.381: C202.1 C204.2 T22.3
N18885440: length 2.7
  TOP w0.381: C214.1 C216.2 T23.3
N18893180: length 3.2
  TOP w0.381: C133.1 45.62,41.3 arc(45.86,40.58) 45.81,39.83 T5.6
N18962088:
  vias: v1(182.09,33.17) v1(182.07,32.21) v1(183.11,33.17) v1(183.08,32.21) v1(184.02,32.21) v1(184.05,33.17)
N18962090:
  vias: v1(178.75,27.42)
N18962122: length 0.3
  BOTTOM w0.381: v1(177.45,27.42) 177.65,27.61 R222.2
N18962132: length 0.2
  BOTTOM w0.381: R223.2 176.73,27.49 v1(176.8,27.42)
N18962213: length 0.4
  BOTTOM w0.381: v1(175.5,28.72) 175.71,28.72 R224.2
N18963933:
  vias: v1(114.12,9.42)
N18963939: length 2.2
  TOP w0.305: v1(112.5,15.47) 112.42,15.39 C353.1 112.42,14.61 v1(112.5,14.53) 112.5,13.47 C451.1
  vias: v1(112.57,13.64) v1(112.57,12.7) v1(114.35,15.49) v1(114.35,14.53) v1(114.35,13.59) v1(115.6,15.52) v1(115.6,14.55) v1(115.6,13.61)
N18963949:
  vias: v1(119.35,10.09)
N18963966: length 0.3
  TOP w0.381: U20.6 v1(115.4,8.14)
  BOTTOM w0.381: v1(115.4,8.14) 115.27,8.27 R253.2
N18963972: length 1.8
  TOP w0.305: C358.1 112.6,10.74 U20.3
N18963976: length 0.2
  BOTTOM w0.381: R254.2 116.21,8.25 v1(116.09,8.14)
N18964074: length 2.6
  TOP w0.254: R249.1 117.45,14.73 R250.1
  TOP w0.305: R249.1 116.54,16.81 PP8.1
N18964185: length 0.5
  BOTTOM w0.305: v1(117.55,15.65) 117.49,15.58 U19.1
N18964329: length 1.9
  TOP w0.305: U20.13 121.21,10.74 C361.1
N18992157: length 0.1
  BOTTOM w0.305: v1(129.1,21.07) 129.03,21.14 R282.2
N18992183: length 2.2
  TOP w0.203: C456.1 126.21,26.78 C415.1 v1(126.47,28.65)
  vias: v1(126.34,26.95) v1(126.34,26.01) v1(126.44,27.81) v1(127.94,27.74) v1(127.97,28.6) v1(128.02,26.85) v1(128.02,26.01) v1(129.08,26.85) v1(129.08,26.01) v1(129.21,28.6) v1(129.18,27.74)
N18992193:
  vias: v1(133.01,23.02)
N18992197: length 0.2
  BOTTOM w0.305: v1(129.75,21.07) 129.87,21.19 R283.2
N18992199: length 1.7
  TOP w0.305: U29.3 126.31,23.67 C419.1
N18992203:
  vias: v1(131.05,21.07)
N18992243: length 2.8
  TOP w0.254: R281.1 131.01,27.74 R280.1
  TOP w0.305: R280.1 PP28.1
N18992297: length 0.5
  BOTTOM w0.305: U30.1 131.07,28.61 v1(131.11,28.65)
N18992349: length 1.8
  TOP w0.305: C421.1 134.8,23.67 U29.13
N18994871: length 0.3
  TOP w0.305: U29.10 131.76,21.01 v1(131.95,21.01)
N19007167: length 2.7
  TOP w0.305: v3(153.21,7.58) 153.21,7.37 v1(152.65,6.81)
  BOTTOM w0.305: v3(153.21,7.58) 153.21,6.98 R234.2 152.7,6.76 v1(152.65,6.81)
  vias: v1(148.56,8.05) v1(148.56,6.96) v1(149.4,7.47) v1(149.94,4.88) v1(149.94,2.79) v1(149.96,3.84) v1(150.85,4.88) v1(150.88,3.84) v1(150.85,2.79) v1(151.82,4.9) v1(151.84,3.86) v1(151.82,2.82)
N19009214: length 3
  TOP w0.305: C328.1 154.71,6.31 v3(154.71,7.22) U16.20
  BOTTOM w0.305: v3(154.71,7.94) v3(154.71,7.22) 154.71,7.01 R234.1
N19009493: length 3.4
  TOP w0.203: U16.21 155.21,6.96 155.39,6.78 155.95,6.78 156.15,6.57 C501.1 156.96,5.75 Q26.3
N19010016: length 1
  TOP w0.305: R235.1 153.1,14.09 C327.2
N19010394: length 7.3
  BOTTOM w0.305: 147.42,19.33 147.5,19.41 153.64,19.41 v1(154.36,18.69)
  vias: v1(145.54,14.2) v1(145.54,13.34) v1(146.74,14.22) v1(146.71,13.36) v1(147.4,18.01) v1(147.4,16.69) v1(147.4,15.49) v1(147.83,13.36) v1(147.85,14.2) v1(149,14.2) v1(149.02,13.36)
N19011515: length 1.4
  BOTTOM w0.254: v1(143.48,10.87) 144.4,11.79 R241.1
N19011541:
  vias: v1(139.17,14.81) v1(139.17,13.92) v1(140.31,14.81) v1(140.3,13.93) v1(140.89,18.62) v1(140.89,17.6) v1(140.89,16.71) v1(141.14,13.8) v1(141.15,19.38) v1(141.78,18.24) v1(141.78,17.22) v1(142.11,13.8) v1(142.16,19.13)
N19011602:
  vias: v1(143.48,11.89)
N19016825: length 0.9
  TOP w0.305: C338.2 154.38,15.93 R237.1
N19016841: length 3.5
  TOP w0.305: 155.27,16.92 R239.1 154.38,16.84 C338.1 R240.2 154.38,17.7 R301.2 155.27,16.92
N19016961: length 0.9
  TOP w0.305: R245.1 C342.2
N19016975: length 3.9
  TOP w0.305: C342.1 C340.1 156.21,12.75 155.71,12.25 U16.1
N19024858:
  vias: v1(150.09,13.92)
N19030259: length 0.4
  BOTTOM w0.305: v3(153.72,7.47) 153.85,7.59 R244.1
N19030918: length 1.8
  TOP w0.203: C341.1 154.21,6.44 U16.19
N19075291: length 0.1
  BOTTOM w0.254: R31.2 51.16,69.51 v1(51.15,69.5)
N19075362:
  vias: v1(51.15,68.7)
N19075631: length 132.7
  L6_SIG w0.127: v1(68.92,118.8) 68.92,119.17 69.94,120.19 70.72,120.19 70.94,119.96 132.18,119.96 136.96,115.19 J11.1
  BOTTOM w0.102: 55.55,71.5 55.55,69.34 55.28,69.07 54.99,69.07 54.74,68.82 54.74,68.53 54.51,68.3 54.22,68.3 53.95,68.03 53.95,65.15 53.55,64.75 v1(53.55,64.7)
  BOTTOM w0.127: 55.55,71.5 55.72,71.67 55.72,75.73 58.86,78.87 59.17,78.87 62.2,81.9 62.2,87.72 62.82,88.34 62.82,97.37 64.58,99.12 64.58,99.52 65.36,100.31 65.77,100.31 67.47,102.01 67.47,106.18 66.91,106.74 66.91,107.29 67.51,107.88 67.51,113.84 68.92,115.25 v1(68.92,118.8)
N19075640: length 142.7
  L4_SIG w0.102: 65.15,61.9 59.56,61.9 59.16,61.5 v1(59.15,61.5)
  L4_SIG w0.127: 65.15,61.9 67.87,61.9 72.52,57.25 138.68,57.25 v1(139.95,58.52)
  L8_PWR_SIG w0.127: v1(139.95,58.52) 139.95,58.86 138.49,60.32 138.15,60.32 137.49,60.99 137.49,81.31 137.59,81.41 137.59,92.15 136.78,92.96 136.78,104.9 136.79,104.91 136.79,110.78 136.78,110.8 136.78,111.86 139.5,114.58 J11.3
N19075649: length 136.2
  TOP w0.127: J11.5 142.93,115.04 147.04,110.92 147.04,103.84 144.92,101.71 144.92,88.3 144.68,88.06 v1(144.68,87.96)
  L4_SIG w0.102: 65.15,67.52 63.83,67.52 63.53,67.22 63.53,66.14 63.27,65.88 59.53,65.88 v1(59.15,65.5)
  L4_SIG w0.127: v1(144.17,70.76) 143.84,70.76 141.92,68.85 81.03,68.85 80.96,68.92 74.26,68.92 72.85,67.52 65.15,67.52
  L8_PWR_SIG w0.127: v1(144.68,87.96) 144.77,87.87 144.77,81.98 144.46,81.68 144.46,80.23 144.68,80.02 144.68,75.46 144.69,75.44 144.69,71.29 v1(144.17,70.76)
N19075658: length 134.3
  L4_SIG w0.102: v1(63.95,63.1) 64.21,63.1 64.59,63.48 65.15,63.48
  L4_SIG w0.127: 65.15,63.48 67.47,63.48 68.07,64.08 71.83,64.08 75.58,60.34 138.21,60.34 139.32,61.45 v1(139.32,61.72)
  L8_PWR_SIG w0.127: J11.7 144.58,114.83 142.39,112.65 142.39,106.72 142.41,106.71 142.41,101.28 142.38,101.26 142.38,92.47 142.77,92.08 142.77,89.94 142.56,89.72 142.56,89.35 142.77,89.13 142.77,82.67 143.09,82.35 143.09,81.98 142.67,81.57 142.67,77.27 139.34,73.94 139.34,61.75 v1(139.32,61.72)
N19075667: length 136.3
  L4_SIG w0.102: 65.15,65.08 64.59,65.08 64.37,64.86 64.37,64.57 63.95,64.15 v1(63.95,63.9)
  L4_SIG w0.127: v1(146.91,64.77) 146.9,64.76 146.11,64.76 144.7,63.35 75.79,63.35 73.81,65.33 65.4,65.33 65.15,65.08
  L8_PWR_SIG w0.127: v1(146.91,64.77) 146.89,64.8 146.89,84.68 147.85,85.65 147.85,91.74 147.02,92.58 147.02,114.94 J11.9
N19080738: length 10.2
  TOP w0.508: JP1.2 112.39,99.46 C248.2 C246.2 C243.2 C242.2 110.88,108.12 FB1.1
N19081029:
  vias: v1(109.82,110.83)
N19083254: length 36.4
  L8_PWR_SIG w0.127: v1(113.06,82.6) 112.97,82.51 97.37,82.51 95.22,84.66 v1(94.56,84.66)
  BOTTOM w0.127: v1(94.56,84.66) 92.27,86.96 92.27,93.83 92.95,94.51 93.42,94.51 94.59,95.68 95.73,95.68 97.31,94.11 U3.31
N19083268: length 17
  TOP w0.127: v1(113.06,84.51) 112.52,85.04 112.52,92.81 109.32,96.01 v1(108.79,96.01)
  BOTTOM w0.127: U3.48 106.09,95.8 106.57,96.28 108.52,96.28 v1(108.79,96.01)
N19083286: length 7.5
  BOTTOM w0.127: U3.59 108.13,89.6 108.46,89.28 110.15,89.28 113.03,86.4 R198.2
N19083328: length 6.8
  BOTTOM w0.127: U3.58 108.52,90.11 108.78,89.85 110.43,89.85 111.96,88.32 R197.2
N19083344:
  vias: v3(100.58,86.61)
N19083346: length 1.2
  TOP w0.305: v3(101.09,86.28) 101.09,85.5 C268.1
N19083364: length 1.5
  TOP w0.305: v3(101.57,85.95) 101.6,85.98 v3(101.6,86.61)
  TOP w0.381: v3(98.6,95.1) 98.6,95.68 v3(98.4,95.88)
  vias: v3(98.58,95.51) v3(100.08,95.77) v3(100.08,95.1)
N19083444: length 0.7
  TOP w0.381: v3(101.6,95.1) 101.6,95.8 v3(101.59,95.82)
N19083446: length 0.6
  TOP w0.381: v3(104.57,95.12) FB9.2 104.57,95.73 v3(104.6,95.76)
N19083508: length 1.1
  TOP w0.203: v3(105.59,95.31) v3(105.59,95.66)
  BOTTOM w0.305: v3(105.59,95.31) U3.47 v3(105.59,95.66) v3(105.59,96.02)
N19083566: length 0.6
  TOP w0.381: v3(97.38,89.13) 97.41,89.1 v3(97.99,89.1)
N19083568: length 4.7
  TOP w0.305: v3(97.41,87.12) 97.37,87.08 97.37,86.72 ; v3(97.41,87.12) 97.46,87.07 97.99,87.07 ; v3(97.41,87.12) 97.43,87.12 97.56,87.25 97.82,87.25 97.99,87.07 ; v3(97.41,87.12) 97.41,86.72 ; 97.41,86.72 97.68,86.72 v3(98.06,87.1) ; 97.41,86.72 97.37,86.72 ; 97.37,86.72 FB5.2 97.67,86.29 98.04,86.66 98.04,87.02 97.99,87.07
N19083616: length 6.2
  TOP w0.305: 107.07,86.32 107.07,86.11 FB11.2 ; 107.07,86.32 107.08,86.32 ; 107.07,86.32 106.86,86.32 106.68,86.5 106.68,87.01 v3(106.59,87.1) 106.86,87.1 ; 106.86,87.1 107.08,87.1 ; 106.86,87.1 106.86,86.56 107.08,86.34 ; 107.08,87.1 107.08,86.34 ; 107.08,87.1 v3(107.25,87.1) ; 107.08,87.1 107.24,86.94 ; 107.08,86.34 107.08,86.32 ; FB11.2 107.31,86.13 107.53,86.35 107.53,86.78 107.36,86.94 107.24,86.94 ; FB11.2 107.24,86.18 107.24,86.32 ; 107.08,86.32 107.24,86.32 ; 107.24,86.94 107.24,86.32
N19083618: length 2.1
  TOP w0.381: v3(107.44,92.58) 106.4,92.58 v3(106.78,92.61)
  BOTTOM w0.305: v3(107.44,92.58) 107.42,92.61 U3.53 106.78,92.61 v3(106.78,92.61)
N19083707: length 0.8
  TOP w0.381: v3(97.99,91.59) FB4.2
  vias: v3(97.38,91.63)
N19086842: length 4.1
  BOTTOM w0.203: C229.1 96.76,83.29 R168.1 97.49,84.01 97.99,84.01 98.67,84.69 98.67,85.37 98.58,85.46 U3.16
N19086844: length 4.3
  BOTTOM w0.203: C228.1 97.89,83.51 R167.1 99,84.56 99,85.37 99.08,85.46 U3.15
N19098122: length 1.8
  TOP w0.381: C127.2 44.73,42.88 L3.2 45.03,43.94 C129.2
N19098132: length 1.8
  TOP w0.381: C130.2 46.04,43.72 L3.1 45.7,42.46 C133.2
N19098142: length 1.7
  TOP w0.381: 46.09,44.5 46.36,44.78 L5.1 46.63,45.85 R58.2
N19098149: length 1.8
  TOP w0.381: R48.2 45.66,46.12 L5.2 45.33,45.01 C129.1
N19098687: length 0.7
  TOP w0.381: R48.1 C131.2
N19098701: length 0.7
  TOP w0.381: C136.2 R58.1
N19189047: length 6.1
  TOP w0.381: v1(92.99,90.17) 91.39,90.17 90.35,91.21 90.35,92.08 89.44,92.99 J27.1
N19189049: length 6.1
  TOP w0.381: J28.1 92.71,94.98 91.77,94.04 91.77,93.05 92.99,91.83 v1(92.99,90.78)
N19191731: length 1.4
  BOTTOM w0.381: T2.2 23.04,63.26 arc(22.56,63.16) R4.2
N19192217: length 5
  BOTTOM w0.381: R8.2 28.18,62.62 28.37,62.81 31.53,62.81 R9.1 C7.1
N19192242: length 1.5
  BOTTOM w0.381: T3.2 34.51,62.33 arc(33.97,62.44) C7.2
N19192342: length 1.4
  BOTTOM w0.381: T2.4 25.53,62.55 25.54,62.55 26.55,62.55 R8.1
N19192872: length 4.9
  BOTTOM w0.381: R1.2 28.22,64.03 28.35,64.16 R2.1 C1.1
N19192989: length 1.4
  BOTTOM w0.381: R1.1 26.48,63.97 T2.6
N19193468: length 127
  L4_SIG w0.102: v1(51.15,57.5) 50.77,57.12 49.59,57.12 49.15,57.55
  L4_SIG w0.127: 49.15,57.55 47.28,59.42 47.28,70.9 47.08,71.11 47.08,75.92 46.72,76.28 46.72,77.33 46.87,77.47 46.87,82.18 45.77,83.28 45.77,95.56 55.14,104.94 56.45,104.94 60,108.49 65.14,108.49 65.41,108.77 67.16,108.77 67.21,108.71 95.03,108.71 95.07,108.75 95.43,108.75 95.47,108.71 110.11,108.71 111.12,109.73 111.12,110.31 117.81,116.99 v1(118.39,116.99)
  BOTTOM w0.127: SW1.2 R17.2 v1(118.39,116.99)
N19234861: length 0.6
  TOP w0.381: v3(103.09,95.77) 103.07,95.75 v3(103.07,95.12)
N19245147: length 3.6
  TOP w0.381: R54.2 R52.2 39.56,23.85 C132.1 L6.2
N19261159: length 19
  BOTTOM w0.381: v1(17.93,59.54) 18.37,59.97 arc(18.69,60.19) 19.06,60.26 35.92,60.26 arc(36.3,60.34) R3.2
N19261175: length 19
  BOTTOM w0.381: R10.2 36.6,64.11 34.87,65.84 arc(33.88,66.5) 32.7,66.74 19.47,66.74 arc(19.12,66.81) 18.82,67.01 v1(18.67,67.16)
N19261803: length 29
  BOTTOM w0.381: v1(30.59,36.41) 31.69,37.06 arc(33.24,38.24) 34.49,39.73 34.49,39.73 arc(35.19,40.77) 35.92,41.79 36.9,43.25 arc(36.9,43.26) 36.91,43.26 39.52,46.87 arc(40.27,48.23) 40.66,49.72 41.42,55.25 arc(41.8,56.83) 42.49,58.3 44.03,60.92 R11.2
N19261938: length 29
  BOTTOM w0.381: v1(20.94,47.86) 21.02,47.82 23.04,48.58 arc(26.38,50.05) 29.52,51.9 39.28,58.43 arc(40.17,59.24) 40.8,60.26 41.73,62.45 arc(42.3,63.21) 43.15,63.63 R14.2
N19265268: length 27.2
  L4_SIG w0.102: v1(59.15,59.1) 59.2,59.1 59.59,59.49 65.15,59.49
  L4_SIG w0.127: 65.15,59.49 67.11,59.49 79.65,46.94 v1(80.95,46.94)
N19265271: length 34.6
  L4_SIG w0.102: 57.92,55.36 57.92,55.45 57.94,55.47 57.94,57.1 58.34,57.5 v1(58.35,57.5)
  L4_SIG w0.127: v1(82.8,38.81) 81.94,38.81 69.65,51.1 62.58,51.1 62.17,51.5 62.17,51.99 60.93,53.24 60.53,53.24 59.59,54.17 58.61,54.17 58.35,54.43 58.35,54.63 57.92,55.05 57.92,55.36
N19265297: length 37.5
  BOTTOM w0.102: 57.56,55.36 56.34,56.58 56.34,58.72 55.96,59.1 v1(55.95,59.1)
  BOTTOM w0.127: R309.2 81.84,38.1 76.47,38.1 70.24,44.32 69.02,44.32 65.37,47.98 64.48,47.98 57.56,54.89 57.56,55.36
N19265300: length 35.3
  L4_SIG w0.102: 59.68,55.36 58.73,56.31 58.73,57.66 58.48,57.91 56.31,57.91 55.95,58.27 v1(55.95,58.3)
  L4_SIG w0.127: v1(82.83,40.49) 80.95,40.49 69.1,52.34 62.7,52.34 60.79,54.24 60.35,54.24 60.09,54.5 60.09,54.95 59.68,55.36
N19265317: length 23.6
  L4_SIG w0.102: v1(59.15,67.9) 59.57,68.32 60.91,68.32 61.17,68.58 61.17,70.46 61.42,70.71 65.15,70.71
  L4_SIG w0.127: 65.15,70.71 70.91,70.71 75.92,75.72 75.92,76.61 v1(77.04,77.72)
N19265320: length 25.2
  BOTTOM w0.102: v1(58.35,69.5) 58.62,69.5 58.99,69.87 59.05,69.87 59.26,69.88 59.58,70.2 59.58,71.5
  BOTTOM w0.127: 59.58,71.5 59.58,73.84 64.98,79.25 65.72,79.25 66.48,80.01 R312.2
N19265379: length 31.1
  L4_SIG w0.102: 56.37,71.5 56.37,68.32 v1(55.95,67.9)
  L4_SIG w0.127: 56.37,71.5 56.37,71.69 56.77,72.1 56.77,74.25 57.51,74.99 57.51,75.59 64.95,83.02 74.03,83.02 74.38,83.36 v1(77.06,83.36)
N19265382: length 28.8
  BOTTOM w0.102: v1(55.95,68.7) 56.2,68.7 56.59,69.09 57.67,69.09 57.96,69.38 57.96,69.64 58.25,69.93 58.51,69.93 58.72,70.14 58.72,71.5
  BOTTOM w0.127: R314.2 66.87,81.81 64.94,79.88 64.94,79.86 59.17,74.09 59.17,73.27 58.91,73.01 58.85,73.01 58.72,72.89 58.72,71.5
N19265545: length 31.1
  L4_SIG w0.102: 65.15,56.29 59.82,56.29 59.57,56.54 59.57,57.88 v1(59.15,58.3)
  L4_SIG w0.127: v1(82.8,42.11) 82.73,42.19 79.96,42.19 65.86,56.29 65.15,56.29
N19265548: length 29.8
  L4_SIG w0.102: v1(56.75,58.3) 56.75,58.3 57.17,58.72 58.51,58.72 58.77,58.98 58.77,60.12 58.97,60.32 65.15,60.32
  L4_SIG w0.127: 65.15,60.32 66.91,60.32 75.53,51.7 75.53,51.58 78.85,48.26 v1(79.93,48.26)
N19265574: length 28.5
  L4_SIG w0.102: 65.15,57.12 60.33,57.12 v1(59.95,57.5)
  L4_SIG w0.127: v1(82.83,43.92) 79.6,43.92 66.4,57.12 65.15,57.12
N19265577: length 28.5
  L4_SIG w0.102: v1(59.95,59.1) 60.35,58.7 65.15,58.7
  L4_SIG w0.127: v1(82.83,45.44) 79.4,45.44 66.14,58.7 65.15,58.7
N19265594: length 24.9
  L4_SIG w0.102: v1(59.15,68.7) 59.17,68.7 59.56,69.09 59.56,71.5
  L4_SIG w0.127: v1(77.04,79.22) 76.79,79.47 66.77,79.47 63.81,76.52 63.81,76.39 61.88,74.46 61.88,74.17 61.45,73.73 60.51,73.73 59.56,72.79 59.56,71.5
N19265597: length 29.2
  L4_SIG w0.102: 57.17,71.5 57.17,69.13 56.75,68.71 v1(56.75,68.7)
  L4_SIG w0.127: 57.17,71.5 57.17,71.87 57.33,72.03 57.33,73.95 58.91,75.53 58.91,76.27 62.45,79.81 63.43,79.81 66.2,82.58 v1(77.04,82.58)
N19265616: length 22.8
  BOTTOM w0.102: 60.33,71.5 60.33,69.87 v1(59.95,69.5)
  BOTTOM w0.127: R304.2 74.99,76.96 74.33,77.62 65.18,77.62 61.38,73.82 60.97,73.82 60.14,72.99 60.14,71.68 60.33,71.5
N19265619: length 22
  L4_SIG w0.102: 65.15,69.9 62.18,69.9 61.97,69.69 61.97,67.78 61.71,67.52 60.33,67.52 v1(59.95,67.9)
  L4_SIG w0.127: 65.15,69.9 65.16,69.91 70.75,69.91 v1(77.04,76.2)
N19270100: length 6.1
  TOP w0.381: J29.1 93.04,83.23 93.03,83.24 93.03,83.69 93.04,83.7 93.04,84.3 92.09,85.25 92.09,86.01 93.6,87.52 v1(93.6,88.29)
N19270102: length 6.1
  TOP w0.381: J30.1 89.25,85.58 92.5,88.84 93.38,88.84 93.45,88.9 v1(93.6,88.9)
N19353777: length 3.2
  TOP w0.381: T5.4 43.33,40.41 arc(43.7,41.15) 44.32,41.7 C127.1
N19392140: length 2
  BOTTOM w0.381: C6.2 43.89,71.5 arc(43.67,71.65) 43.4,71.7 T1.6
N19392142: length 18.8
  L6_SIG w0.102: v1(53.55,63.9) 53.94,64.29 55.28,64.29 55.57,64.58 55.57,70.42 55.27,70.72 49.26,70.72 49.15,70.62
  L6_SIG w0.127: v1(45.24,70.74) 45.36,70.62 46,70.62 46.08,70.54 49.07,70.54 49.15,70.62
N19392187: length 17.8
  L6_SIG w0.102: v1(53.55,63.1) 53.13,63.52 53.13,64.82 53.39,65.08 54.56,65.08 54.73,65.25 54.73,69.66 54.51,69.88 49.3,69.88 49.15,70.02
  L6_SIG w0.127: v1(45.24,70.13) 45.29,70.19 45.82,70.19 45.9,70.1 49.07,70.1 49.15,70.02
N19392195: length 2.2
  BOTTOM w0.381: T1.3 39.71,69.24 C3.1
N19392206: length 37.2
  BOTTOM w0.381: J3.1 4.8,70.23 arc(6.28,70.52) 7.53,71.36 8.28,72.11 arc(9.38,72.84) 10.67,73.1 30.95,73.1 arc(31.88,72.92) 32.66,72.39 R6.2 36.4,69.24 C3.2
N19393571: length 12.9
  TOP w0.127: R21.1 67.28,54.18 65.15,56.31 61.39,56.31 61.16,56.54 61.16,56.56 61.14,56.58 61.14,60.3 61.54,60.7 U1.G5
N19402254: length 25.9
  TOP w0.127: J36.10 173.79,86.26 178.03,90.5 178.03,93.45 181.02,96.44 182.91,96.44 183.81,97.34 U5.54
N19402263: length 29.3
  TOP w0.127: J36.7 167.49,87.3 174.19,87.3 177.52,90.63 177.52,93.6 178.82,94.89 178.82,97.26 178.46,97.61 178.46,99.75 178.77,100.05 182.58,100.05 183.31,100.79 U5.53
N19402272: length 30.2
  TOP w0.127: U5.52 182.81,100.9 182.4,100.48 178.54,100.48 178.05,100 178.05,97.36 178.4,97.02 178.4,95.06 176,92.66 173,92.66 170.44,90.09 168.02,90.09 167.46,89.53 167.46,88.39 166.52,87.45 165.1,87.45 J36.4
N19402281: length 29.9
  TOP w0.127: J36.1 161.37,86.31 162.81,87.76 164.67,87.76 165.2,88.29 165.2,88.9 166.67,90.37 170.13,90.37 172.87,93.12 175.51,93.12 177.55,95.15 177.55,100.33 179.44,102.22 U5.48
N19403607: length 8.4
  TOP w0.127: U6.18 184.78,119.54 188.87,115.44 188.87,113.43 U5.17
N19403614: length 6.9
  TOP w0.127: U5.19 187.81,115.49 184.73,118.57 184.31,118.57 U6.16
N19403621: length 5.3
  TOP w0.127: U6.14 184.29,117.53 184.73,117.53 186.31,115.95 U5.22
N19403628: length 3.7
  TOP w0.127: U6.12 184.53,116.54 185.31,115.75 U5.24
N19407936: length 6.3
  BOTTOM w0.127: v3(179.44,106.5) 178.73,106.5 178.23,105.99 178.23,103.1 177.37,102.24 v3(176.61,102.24)
